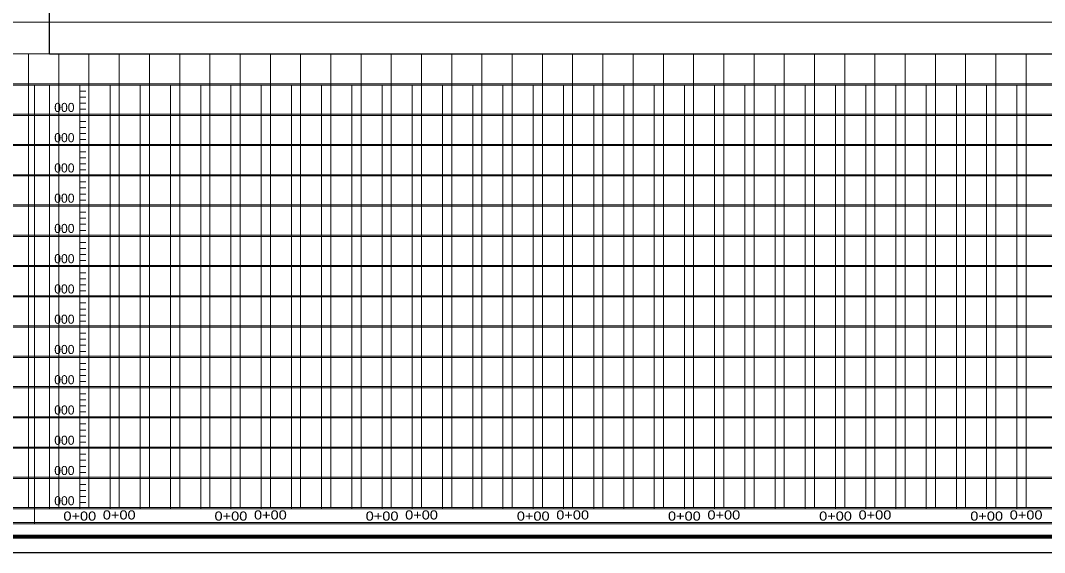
# Model space of a CAD drawing. Extents: x 2246932 to 2264252, y 7095151 to 7098651.
# Drawn here: x 2252265 to 2255652, y 7095151 to 7096909 of the extents above; entities that cross this region are included whole.
import ezdxf
from ezdxf.enums import TextEntityAlignment as Align

# ---------------------------------------------------------------- set-up
doc = ezdxf.new("R2010")
doc.units = 0
doc.header["$LTSCALE"] = 12
for name, color, linetype, lineweight in [('1', 7, 'Continuous', 80), ('59', 7, 'Continuous', 13), ('60', 7, 'Continuous', 13), ('62', 7, 'Continuous', 13), ('63', 7, 'Continuous', 25)]:
    doc.layers.add(name, color=color, linetype=linetype, lineweight=lineweight)
doc.layers.add('22', color=7, linetype='Continuous')
doc.layers.add('23', color=7, linetype='Continuous')

msp = doc.modelspace()

# ---------------------------------------------------------------- linework, layer by layer
at = {"layer": '1'}
msp.add_line((2247157.09, 7095203.35), (2264052.09, 7095203.35), dxfattribs=at)
at = {"layer": '1', "lineweight": 25}
msp.add_line((2247104.59, 7095150.85), (2264104.59, 7095150.85), dxfattribs=at)
at = {"layer": '59'}
for p, q in [((2247310.97, 7096695.64), (2262610.97, 7096695.64)), ((2252360.97, 7095295.64), (2252360.97, 7096695.64)), ((2252460.97, 7096695.64), (2252460.97, 7095295.64)), ((2252560.97, 7095295.64), (2252560.97, 7096695.64)), ((2252660.97, 7096695.64), (2252660.97, 7095995.64)), ((2252760.97, 7096695.64), (2252760.97, 7095995.64)), ((2252860.97, 7096695.64), (2252860.97, 7095995.64)), ((2252960.97, 7096695.64), (2252960.97, 7095995.64)), ((2253060.97, 7096695.64), (2253060.97, 7095995.64)), ((2253160.97, 7096695.64), (2253160.97, 7095995.64)), ((2253260.97, 7096695.64), (2253260.97, 7095995.64)), ((2253360.97, 7096695.64), (2253360.97, 7095995.64)), ((2253460.97, 7096695.64), (2253460.97, 7095995.64)), ((2253560.97, 7096695.64), (2253560.97, 7095995.64)), ((2253660.97, 7096695.64), (2253660.97, 7095995.64)), ((2253760.97, 7096695.64), (2253760.97, 7095995.64)), ((2253860.97, 7096695.64), (2253860.97, 7095995.64)), ((2253960.97, 7096695.64), (2253960.97, 7095995.64)), ((2254060.97, 7096695.64), (2254060.97, 7095995.64)), ((2254160.97, 7096695.64), (2254160.97, 7095995.64)), ((2254260.97, 7096695.64), (2254260.97, 7095995.64)), ((2254360.97, 7096695.64), (2254360.97, 7095995.64)), ((2254460.97, 7096695.64), (2254460.97, 7095995.64)), ((2254560.97, 7096695.64), (2254560.97, 7095995.64)), ((2254660.97, 7096695.64), (2254660.97, 7095995.64)), ((2254760.97, 7096695.64), (2254760.97, 7095995.64)), ((2254860.97, 7096695.64), (2254860.97, 7095995.64)), ((2254960.97, 7096695.64), (2254960.97, 7095995.64)), ((2255060.97, 7096695.64), (2255060.97, 7095995.64)), ((2255160.97, 7096695.64), (2255160.97, 7095995.64)), ((2255160.97, 7096695.64), (2255160.97, 7095995.64)), ((2255260.97, 7096695.64), (2255260.97, 7095995.64)), ((2255260.97, 7096695.64), (2255260.97, 7095995.64)), ((2255360.97, 7096695.64), (2255360.97, 7095995.64)), ((2255460.97, 7096695.64), (2255460.97, 7095995.64)), ((2255560.97, 7096695.64), (2255560.97, 7095995.64)), ((2252660.97, 7095995.64), (2252660.97, 7095295.64)), ((2252760.97, 7095995.64), (2252760.97, 7095295.64)), ((2252860.97, 7095995.64), (2252860.97, 7095295.64)), ((2252960.97, 7095995.64), (2252960.97, 7095295.64)), ((2253060.97, 7095995.64), (2253060.97, 7095295.64)), ((2253160.97, 7095995.64), (2253160.97, 7095295.64)), ((2253260.97, 7095995.64), (2253260.97, 7095295.64)), ((2253360.97, 7095995.64), (2253360.97, 7095295.64)), ((2253460.97, 7095995.64), (2253460.97, 7095295.64)), ((2253560.97, 7095995.64), (2253560.97, 7095295.64)), ((2253660.97, 7095995.64), (2253660.97, 7095295.64)), ((2253760.97, 7095995.64), (2253760.97, 7095295.64)), ((2253860.97, 7095995.64), (2253860.97, 7095295.64)), ((2253960.97, 7095995.64), (2253960.97, 7095295.64)), ((2254060.97, 7095995.64), (2254060.97, 7095295.64)), ((2254160.97, 7095995.64), (2254160.97, 7095295.64)), ((2254260.97, 7095995.64), (2254260.97, 7095295.64)), ((2254360.97, 7095995.64), (2254360.97, 7095295.64)), ((2254460.97, 7095995.64), (2254460.97, 7095295.64)), ((2254560.97, 7095995.64), (2254560.97, 7095295.64)), ((2254660.97, 7095995.64), (2254660.97, 7095295.64)), ((2254760.97, 7095995.64), (2254760.97, 7095295.64)), ((2254860.97, 7095995.64), (2254860.97, 7095295.64)), ((2254960.97, 7095995.64), (2254960.97, 7095295.64)), ((2255060.97, 7095995.64), (2255060.97, 7095295.64)), ((2255160.97, 7095995.64), (2255160.97, 7095295.64)), ((2255160.97, 7095995.64), (2255160.97, 7095295.64)), ((2255260.97, 7095995.64), (2255260.97, 7095295.64)), ((2255260.97, 7095995.64), (2255260.97, 7095295.64)), ((2255360.97, 7095995.64), (2255360.97, 7095295.64)), ((2255460.97, 7095995.64), (2255460.97, 7095295.64)), ((2255560.97, 7095995.64), (2255560.97, 7095295.64)), ((2262610.97, 7095295.64), (2247310.97, 7095295.64)), ((2262610.97, 7095245.64), (2247310.97, 7095245.64))]:
    msp.add_line(p, q, dxfattribs=at)
for points in [[(2247460.97, 7096595.64), (2262460.97, 7096595.64), (2262610.97, 7096595.64)], [(2247460.97, 7096495.64), (2262460.97, 7096495.64), (2262610.97, 7096495.64)], [(2247460.97, 7096395.64), (2262460.97, 7096395.64), (2262610.97, 7096395.64)], [(2247460.97, 7096295.64), (2262460.97, 7096295.64), (2262610.97, 7096295.64)], [(2247460.97, 7096195.64), (2262460.97, 7096195.64), (2262610.97, 7096195.64)], [(2247454.92, 7096095.64), (2262460.97, 7096095.64), (2262610.97, 7096095.64)], [(2247460.97, 7095995.64), (2262460.97, 7095995.64), (2262610.97, 7095995.64)], [(2247460.97, 7095895.64), (2262460.97, 7095895.64), (2262610.97, 7095895.64)], [(2247460.97, 7095795.64), (2262460.97, 7095795.64), (2262610.97, 7095795.64)], [(2247460.97, 7095695.64), (2262460.97, 7095695.64), (2262610.97, 7095695.64)], [(2247460.97, 7095595.64), (2262460.97, 7095595.64), (2262610.97, 7095595.64)], [(2247460.97, 7095495.64), (2262460.97, 7095495.64), (2262610.97, 7095495.64)], [(2247460.97, 7095395.64), (2262460.97, 7095395.64), (2262610.97, 7095395.64)]]:
    msp.add_lwpolyline(points, dxfattribs=at)
at = {"layer": '60'}
for p, q in [((2252310.97, 7096695.64), (2262610.97, 7096695.64)), ((2252310.97, 7096695.64), (2252310.97, 7095995.64)), ((2252460.97, 7095995.64), (2252460.97, 7096695.64)), ((2252460.97, 7096675.64), (2252480.97, 7096675.64)), ((2252560.97, 7096695.64), (2252560.97, 7095995.64)), ((2252660.97, 7096695.64), (2252660.97, 7095995.64)), ((2252760.97, 7096695.64), (2252760.97, 7095995.64)), ((2252860.97, 7096695.64), (2252860.97, 7095995.64)), ((2252960.97, 7096695.64), (2252960.97, 7095995.64)), ((2253060.97, 7096695.64), (2253060.97, 7095995.64)), ((2253160.97, 7096695.64), (2253160.97, 7095995.64)), ((2253260.97, 7096695.64), (2253260.97, 7095995.64)), ((2253360.97, 7096695.64), (2253360.97, 7095995.64)), ((2253460.97, 7096695.64), (2253460.97, 7095995.64)), ((2253560.97, 7096695.64), (2253560.97, 7095995.64)), ((2253660.97, 7096695.64), (2253660.97, 7095995.64)), ((2253760.97, 7096695.64), (2253760.97, 7095995.64)), ((2253860.97, 7096695.64), (2253860.97, 7095995.64)), ((2253960.97, 7096695.64), (2253960.97, 7095995.64)), ((2254060.97, 7096695.64), (2254060.97, 7095995.64)), ((2254160.97, 7096695.64), (2254160.97, 7095995.64)), ((2254260.97, 7096695.64), (2254260.97, 7095995.64)), ((2254360.97, 7096695.64), (2254360.97, 7095995.64)), ((2254460.97, 7096695.64), (2254460.97, 7095995.64)), ((2254560.97, 7096695.64), (2254560.97, 7095995.64)), ((2254660.97, 7096695.64), (2254660.97, 7095995.64)), ((2254760.97, 7096695.64), (2254760.97, 7095995.64)), ((2254860.97, 7096695.64), (2254860.97, 7095995.64)), ((2254960.97, 7096695.64), (2254960.97, 7095995.64)), ((2255060.97, 7096695.64), (2255060.97, 7095995.64)), ((2255160.97, 7096695.64), (2255160.97, 7095995.64)), ((2255160.97, 7096695.64), (2255160.97, 7095995.64)), ((2255260.97, 7096695.64), (2255260.97, 7095995.64)), ((2255260.97, 7096695.64), (2255260.97, 7095995.64)), ((2255360.97, 7096695.64), (2255360.97, 7095995.64)), ((2255460.97, 7096695.64), (2255460.97, 7095995.64)), ((2255560.97, 7096695.64), (2255560.97, 7095995.64)), ((2252460.97, 7096655.64), (2252480.97, 7096655.64)), ((2252460.97, 7096635.64), (2252480.97, 7096635.64)), ((2252460.97, 7096615.64), (2252480.97, 7096615.64)), ((2252310.97, 7096595.64), (2252460.97, 7096595.64)), ((2252460.97, 7096575.64), (2252480.97, 7096575.64)), ((2252460.97, 7096555.64), (2252480.97, 7096555.64)), ((2252460.97, 7096535.64), (2252480.97, 7096535.64)), ((2252460.97, 7096515.64), (2252480.97, 7096515.64)), ((2252310.97, 7096495.64), (2252460.97, 7096495.64)), ((2252460.97, 7096475.64), (2252480.97, 7096475.64)), ((2252460.97, 7096455.64), (2252480.97, 7096455.64)), ((2252460.97, 7096435.64), (2252480.97, 7096435.64)), ((2252460.97, 7096415.64), (2252480.97, 7096415.64)), ((2252310.97, 7096395.64), (2252460.97, 7096395.64)), ((2252460.97, 7096375.64), (2252480.97, 7096375.64)), ((2252460.97, 7096355.64), (2252480.97, 7096355.64)), ((2252460.97, 7096335.64), (2252480.97, 7096335.64)), ((2252460.97, 7096315.64), (2252480.97, 7096315.64)), ((2252310.97, 7096295.64), (2252460.97, 7096295.64)), ((2252460.97, 7096275.64), (2252480.97, 7096275.64)), ((2252460.97, 7096255.64), (2252480.97, 7096255.64)), ((2252460.97, 7096235.64), (2252480.97, 7096235.64)), ((2252460.97, 7096215.64), (2252480.97, 7096215.64)), ((2252310.97, 7096195.64), (2252460.97, 7096195.64)), ((2252460.97, 7096175.64), (2252480.97, 7096175.64)), ((2252460.97, 7096155.64), (2252480.97, 7096155.64)), ((2252460.97, 7096135.64), (2252480.97, 7096135.64)), ((2252460.97, 7096115.64), (2252480.97, 7096115.64)), ((2252310.97, 7096095.64), (2252460.97, 7096095.64)), ((2252460.97, 7096075.64), (2252480.97, 7096075.64)), ((2252460.97, 7096055.64), (2252480.97, 7096055.64)), ((2252460.97, 7096035.64), (2252480.97, 7096035.64)), ((2252310.97, 7095995.64), (2252310.97, 7095245.64)), ((2252310.97, 7095995.64), (2252460.97, 7095995.64)), ((2252460.97, 7096015.64), (2252480.97, 7096015.64)), ((2252460.97, 7095295.64), (2252460.97, 7095995.64)), ((2252560.97, 7095995.64), (2252560.97, 7095295.64)), ((2252660.97, 7095995.64), (2252660.97, 7095295.64)), ((2252760.97, 7095995.64), (2252760.97, 7095295.64)), ((2252860.97, 7095995.64), (2252860.97, 7095295.64)), ((2252960.97, 7095995.64), (2252960.97, 7095295.64)), ((2253060.97, 7095995.64), (2253060.97, 7095295.64)), ((2253160.97, 7095995.64), (2253160.97, 7095295.64)), ((2253260.97, 7095995.64), (2253260.97, 7095295.64)), ((2253360.97, 7095995.64), (2253360.97, 7095295.64)), ((2253460.97, 7095995.64), (2253460.97, 7095295.64)), ((2253560.97, 7095995.64), (2253560.97, 7095295.64)), ((2253660.97, 7095995.64), (2253660.97, 7095295.64)), ((2253760.97, 7095995.64), (2253760.97, 7095295.64)), ((2253860.97, 7095995.64), (2253860.97, 7095295.64)), ((2253960.97, 7095995.64), (2253960.97, 7095295.64)), ((2254060.97, 7095995.64), (2254060.97, 7095295.64)), ((2254160.97, 7095995.64), (2254160.97, 7095295.64)), ((2254260.97, 7095995.64), (2254260.97, 7095295.64)), ((2254360.97, 7095995.64), (2254360.97, 7095295.64)), ((2254460.97, 7095995.64), (2254460.97, 7095295.64)), ((2254560.97, 7095995.64), (2254560.97, 7095295.64)), ((2254660.97, 7095995.64), (2254660.97, 7095295.64)), ((2254760.97, 7095995.64), (2254760.97, 7095295.64)), ((2254860.97, 7095995.64), (2254860.97, 7095295.64)), ((2254960.97, 7095995.64), (2254960.97, 7095295.64)), ((2255060.97, 7095995.64), (2255060.97, 7095295.64)), ((2255160.97, 7095995.64), (2255160.97, 7095295.64)), ((2255160.97, 7095995.64), (2255160.97, 7095295.64)), ((2255260.97, 7095995.64), (2255260.97, 7095295.64)), ((2255260.97, 7095995.64), (2255260.97, 7095295.64)), ((2255360.97, 7095995.64), (2255360.97, 7095295.64)), ((2255460.97, 7095995.64), (2255460.97, 7095295.64)), ((2255560.97, 7095995.64), (2255560.97, 7095295.64)), ((2252460.97, 7095975.64), (2252480.97, 7095975.64)), ((2252460.97, 7095955.64), (2252480.97, 7095955.64)), ((2252460.97, 7095935.64), (2252480.97, 7095935.64)), ((2252310.97, 7095895.64), (2252460.97, 7095895.64)), ((2252460.97, 7095915.64), (2252480.97, 7095915.64)), ((2252460.97, 7095875.64), (2252480.97, 7095875.64)), ((2252460.97, 7095855.64), (2252480.97, 7095855.64)), ((2252460.97, 7095835.64), (2252480.97, 7095835.64)), ((2252310.97, 7095795.64), (2252460.97, 7095795.64)), ((2252460.97, 7095815.64), (2252480.97, 7095815.64)), ((2252460.97, 7095775.64), (2252480.97, 7095775.64)), ((2252460.97, 7095755.64), (2252480.97, 7095755.64)), ((2252460.97, 7095735.64), (2252480.97, 7095735.64)), ((2252310.97, 7095695.64), (2252460.97, 7095695.64)), ((2252460.97, 7095715.64), (2252480.97, 7095715.64)), ((2252460.97, 7095675.64), (2252480.97, 7095675.64)), ((2252460.97, 7095655.64), (2252480.97, 7095655.64)), ((2252460.97, 7095635.64), (2252480.97, 7095635.64)), ((2252310.97, 7095595.64), (2252460.97, 7095595.64)), ((2252460.97, 7095615.64), (2252480.97, 7095615.64)), ((2252460.97, 7095575.64), (2252480.97, 7095575.64)), ((2252460.97, 7095555.64), (2252480.97, 7095555.64)), ((2252460.97, 7095535.64), (2252480.97, 7095535.64)), ((2252310.97, 7095495.64), (2252460.97, 7095495.64)), ((2252460.97, 7095515.64), (2252480.97, 7095515.64)), ((2252460.97, 7095475.64), (2252480.97, 7095475.64)), ((2252460.97, 7095455.64), (2252480.97, 7095455.64)), ((2252460.97, 7095435.64), (2252480.97, 7095435.64)), ((2252310.97, 7095395.64), (2252460.97, 7095395.64)), ((2252460.97, 7095415.64), (2252480.97, 7095415.64)), ((2252460.97, 7095375.64), (2252480.97, 7095375.64)), ((2252460.97, 7095355.64), (2252480.97, 7095355.64)), ((2252460.97, 7095335.64), (2252480.97, 7095335.64)), ((2262610.97, 7095295.64), (2252310.97, 7095295.64)), ((2252460.97, 7095315.64), (2252480.97, 7095315.64)), ((2262610.97, 7095245.64), (2252310.97, 7095245.64))]:
    msp.add_line(p, q, dxfattribs=at)
for points in [[(2252460.97, 7096595.64), (2262460.97, 7096595.64), (2262610.97, 7096595.64)], [(2252460.97, 7096495.64), (2262460.97, 7096495.64), (2262610.97, 7096495.64)], [(2252460.97, 7096395.64), (2262460.97, 7096395.64), (2262610.97, 7096395.64)], [(2252460.97, 7096295.64), (2262460.97, 7096295.64), (2262610.97, 7096295.64)], [(2252460.97, 7096195.64), (2262460.97, 7096195.64), (2262610.97, 7096195.64)], [(2252454.92, 7096095.64), (2262460.97, 7096095.64), (2262610.97, 7096095.64)], [(2252460.97, 7095995.64), (2262460.97, 7095995.64), (2262610.97, 7095995.64)], [(2252460.97, 7095895.64), (2262460.97, 7095895.64), (2262610.97, 7095895.64)], [(2252460.97, 7095795.64), (2262460.97, 7095795.64), (2262610.97, 7095795.64)], [(2252460.97, 7095695.64), (2262460.97, 7095695.64), (2262610.97, 7095695.64)], [(2252460.97, 7095595.64), (2262460.97, 7095595.64), (2262610.97, 7095595.64)], [(2252460.97, 7095495.64), (2262460.97, 7095495.64), (2262610.97, 7095495.64)], [(2252460.97, 7095395.64), (2262460.97, 7095395.64), (2262610.97, 7095395.64)]]:
    msp.add_lwpolyline(points, dxfattribs=at)
at = {"layer": '62'}
for p, q in [((2263241.45, 7096904.14), (2247941.45, 7096904.14)), ((2247941.45, 7096799.51), (2263241.45, 7096799.51)), ((2252291.45, 7096799.51), (2252291.45, 7095299.51)), ((2252391.45, 7096799.51), (2252391.45, 7095299.51)), ((2252491.45, 7096799.51), (2252491.45, 7095299.51)), ((2252591.45, 7096799.51), (2252591.45, 7095299.51)), ((2252691.45, 7096799.51), (2252691.45, 7095299.51)), ((2252791.45, 7096799.51), (2252791.45, 7095299.51)), ((2252891.45, 7096799.51), (2252891.45, 7095299.51)), ((2252991.45, 7096799.51), (2252991.45, 7095299.51)), ((2253091.45, 7096799.51), (2253091.45, 7095299.51)), ((2253191.45, 7096799.51), (2253191.45, 7095299.51)), ((2253291.45, 7096799.51), (2253291.45, 7095299.51)), ((2253391.45, 7096799.51), (2253391.45, 7095299.51)), ((2253491.45, 7096799.51), (2253491.45, 7095299.51)), ((2253591.45, 7096799.51), (2253591.45, 7095299.51)), ((2253691.45, 7096799.51), (2253691.45, 7095299.51)), ((2253791.45, 7096799.51), (2253791.45, 7095299.51)), ((2253891.45, 7096799.51), (2253891.45, 7095299.51)), ((2253991.45, 7096799.51), (2253991.45, 7095299.51)), ((2254091.45, 7096799.51), (2254091.45, 7095299.51)), ((2254191.45, 7096799.51), (2254191.45, 7095299.51)), ((2254291.45, 7096799.51), (2254291.45, 7095299.51)), ((2254391.45, 7096799.51), (2254391.45, 7095299.51)), ((2254491.45, 7096799.51), (2254491.45, 7095299.51)), ((2254591.45, 7096799.51), (2254591.45, 7095299.51)), ((2254691.45, 7096799.51), (2254691.45, 7095299.51)), ((2254791.45, 7096799.51), (2254791.45, 7095299.51)), ((2254891.45, 7096799.51), (2254891.45, 7095299.51)), ((2254991.45, 7096799.51), (2254991.45, 7095299.51)), ((2255091.45, 7096799.51), (2255091.45, 7095299.51)), ((2255191.45, 7096799.51), (2255191.45, 7095299.51)), ((2255291.45, 7096799.51), (2255291.45, 7095299.51)), ((2255391.45, 7096799.51), (2255391.45, 7095299.51)), ((2255491.45, 7096799.51), (2255491.45, 7095299.51)), ((2255591.45, 7096799.51), (2255591.45, 7095299.51)), ((2259241.45, 7095999.51), (2249441.45, 7095999.51)), ((2252291.45, 7095999.51), (2252291.45, 7095299.51)), ((2252391.45, 7095999.51), (2252391.45, 7095299.51)), ((2263241.45, 7095299.51), (2247941.45, 7095299.51)), ((2263241.45, 7095249.51), (2247941.45, 7095249.51))]:
    msp.add_line(p, q, dxfattribs=at)
for points in [[(2248091.45, 7096699.51), (2263091.45, 7096699.51), (2263241.45, 7096699.51)], [(2248091.45, 7096599.51), (2263091.45, 7096599.51), (2263241.45, 7096599.51)], [(2248091.45, 7096499.51), (2263091.45, 7096499.51), (2263241.45, 7096499.51)], [(2248091.45, 7096399.51), (2263091.45, 7096399.51), (2263241.45, 7096399.51)], [(2248091.45, 7096299.51), (2263091.45, 7096299.51), (2263241.45, 7096299.51)], [(2248091.45, 7096199.51), (2263091.45, 7096199.51), (2263241.45, 7096199.51)], [(2248091.45, 7096099.51), (2263091.45, 7096099.51), (2263241.45, 7096099.51)], [(2248091.45, 7095999.51), (2263091.45, 7095999.51), (2263241.45, 7095999.51)], [(2248091.45, 7095899.51), (2263091.45, 7095899.51), (2263241.45, 7095899.51)], [(2248091.45, 7095799.51), (2263091.45, 7095799.51), (2263241.45, 7095799.51)], [(2248091.45, 7095699.51), (2263091.45, 7095699.51), (2263241.45, 7095699.51)], [(2248091.45, 7095599.51), (2263091.45, 7095599.51), (2263241.45, 7095599.51)], [(2248091.45, 7095499.51), (2263091.45, 7095499.51), (2263241.45, 7095499.51)], [(2248091.45, 7095399.51), (2263091.45, 7095399.51), (2263241.45, 7095399.51)]]:
    msp.add_lwpolyline(points, dxfattribs=at)
at = {"layer": '63'}
msp.add_lwpolyline([(2252360.97, 7098548.06), (2262360.97, 7098548.06), (2262360.97, 7096798.06), (2252360.97, 7096798.06)], close=True, dxfattribs=at)

# ---------------------------------------------------------------- texts
at = {"layer": '22', "width": 1.2}
for p in [(2252591.45, 7095260.11), (2253091.45, 7095260.11), (2253591.45, 7095260.11), (2254091.45, 7095260.11), (2254591.45, 7095260.11), (2255091.45, 7095260.11), (2255591.45, 7095260.11)]:
    msp.add_text('0+00', height=30, dxfattribs=at).set_placement(p, align=Align.CENTER)
at = {"layer": '23'}
for p in [(2252376.52, 7096606.9), (2252376.52, 7096506.9), (2252376.52, 7096406.9), (2252376.52, 7096306.9), (2252376.52, 7096206.9), (2252376.52, 7096106.9), (2252376.52, 7096006.9), (2252376.52, 7095906.9), (2252376.52, 7095806.9), (2252376.52, 7095706.9), (2252376.52, 7095606.9), (2252376.52, 7095506.9), (2252376.52, 7095406.9), (2252376.52, 7095306.9)]:
    msp.add_text('000', height=30, dxfattribs=at).set_placement(p)
at = {"layer": '23', "width": 1.2}
for p in [(2252460.97, 7095256.23), (2252960.97, 7095256.23), (2253460.97, 7095256.23), (2253960.97, 7095256.23), (2254460.97, 7095256.23), (2254960.97, 7095256.23), (2255460.97, 7095256.23)]:
    msp.add_text('0+00', height=30, dxfattribs=at).set_placement(p, align=Align.CENTER)

doc.saveas('drawing.dxf')
